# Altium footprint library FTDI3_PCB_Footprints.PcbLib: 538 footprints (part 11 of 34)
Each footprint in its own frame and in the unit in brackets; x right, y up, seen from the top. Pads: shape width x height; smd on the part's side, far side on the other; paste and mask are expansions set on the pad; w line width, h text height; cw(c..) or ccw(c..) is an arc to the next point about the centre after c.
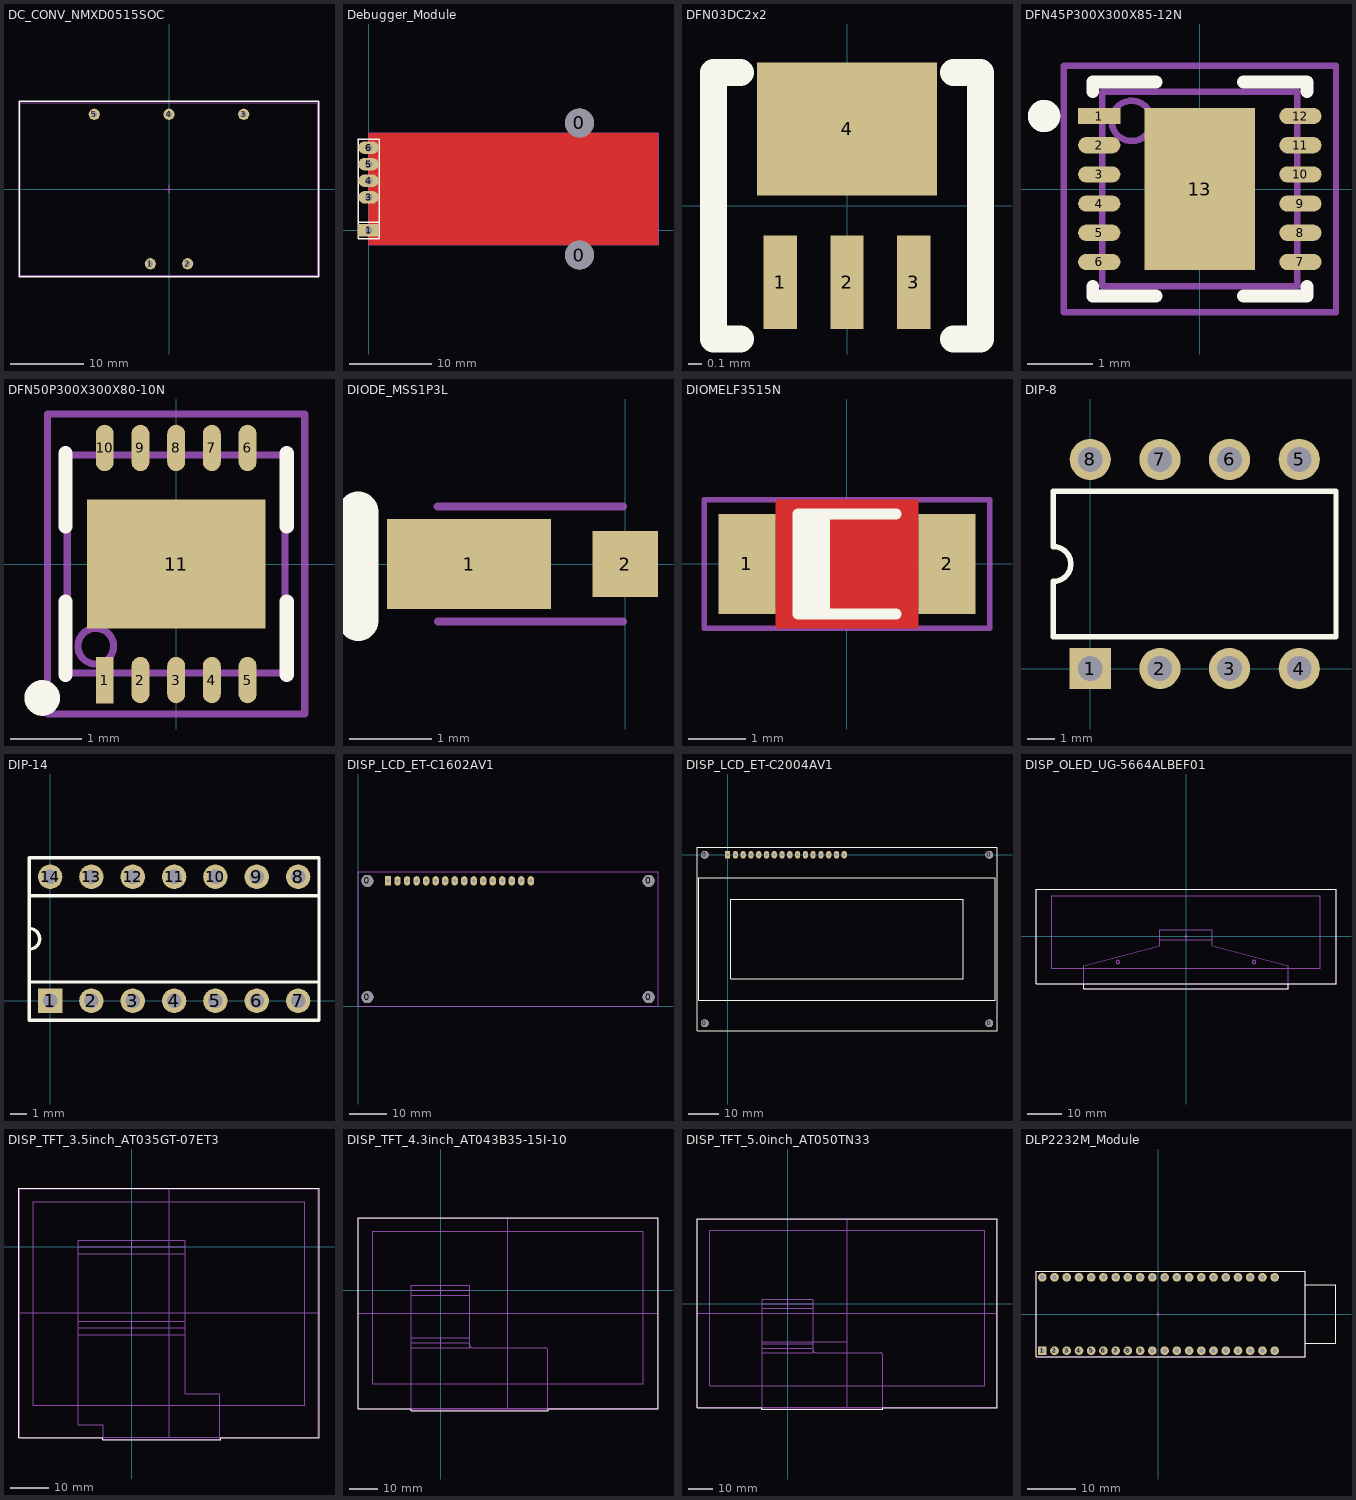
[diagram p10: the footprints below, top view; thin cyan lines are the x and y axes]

## DC_CONV_NMXD0515SOC [mil] "Isolated 5W Regulated Dual Output DC/DC Converter"
pads (5):
  round 60 hole 30: 1(-100,-400) 2(100,-400) 3(400,400) 4(0,400) 5(-400,400)
Top Overlay:
  lines w7.87: -802.76,-468.11 802.76,-468.11 802.76,468.5 -802.76,468.5 -802.76,-468.11
M13_Assembly_Info:
  lines w3.94: -797,-462.5 797,-462.5 797,462.5 -797,462.5 -797,-462.5
M15_Country_Yard:
  lines w3.94: -19.68,0 19.68,0 ; 0,-19.68 0,19.68

## Debugger_Module [mm] "VNC2 Debugger Module"
pads (7):
  round 3.5 hole 3.5 unplated: 0(25.5,-3) 0(25.5,13)
  rect 2.5x1.5 hole 0.9: 1(0,0)
  oval 2.5x1.5 hole 0.9: 3(0,4) 4(0,6) 5(0,8) 6(0,10)
Top Layer:
  pour cut-out: 0,-1.75 35,-1.75 35,11.75 0,11.75
Top Overlay:
  lines w0.2: -1.28,11 1.26,11 ; -1.27,11 -1.27,-1 1.27,-1 1.27,11 ; -1.26,0.98 1.28,0.98
M13_Assembly_Info:
  lines w0.2: 24,-1.75 24,11.75 ; 27,-1.75 27,11.75 ; 0,-1.75 35,-1.75 35,11.75 0,11.75 0,-1.75
3D body: height 1.88, standoff 0, extent 0,-1.75 35,11.75

## DFN03DC2x2 [mm]
pads (4):
  rect 0.25x0.7 smd: 1(-0.5,-0.575) 2(0,-0.575) 3(0.5,-0.575)
  rect 1.35x1 smd: 4(0,0.575)
Top Overlay:
  lines w0.203: -0.8,-1 -1,-1 -1,1 -0.8,1 ; 0.8,-1 1,-1 1,1 0.8,1

## DFN45P300X300X85-12N [mm] "DFN, 12-Leads, Body 3.0x3.0mm (max), Pitch 0.45mm, IPC Medium Density"
height 0.85
pads (13):
  rect 0.65x0.25 smd: 1(-1.55,1.125)
  oval 0.65x0.25 smd: 2(-1.55,0.675) 3(-1.55,0.225) 4(-1.55,-0.225) 5(-1.55,-0.675) 6(-1.55,-1.125) 7(1.55,-1.125) 8(1.55,-0.675) 9(1.55,-0.225) 10(1.55,0.225) 11(1.55,0.675) 12(1.55,1.125)
  rect 1.7x2.5 smd: 13(0,0)
Top Overlay:
  circle w0.25: c-2.4,1.125 r0.125
  lines w0.2: -1.65,-1.5 -1.65,-1.65 -0.675,-1.65 ; -1.65,1.5 -1.65,1.65 -0.675,1.65 ; 0.675,-1.65 1.65,-1.65 1.65,-1.5 ; 0.675,1.65 1.65,1.65 1.65,1.5
M13_Assembly_Info:
  circle w0.1: c-1.05,1.05 r0.31
  lines w0.1: -1.5,-1.5 1.5,-1.5 1.5,1.5 -1.5,1.5 -1.5,-1.5
M15_Country_Yard:
  lines w0.1: -0.5,0 0.5,0 ; 0,-0.5 0,0.5 ; -2.1,-1.9 2.1,-1.9 2.1,1.9 -2.1,1.9 -2.1,-1.9
3D body: height 0.85, standoff 0.02, extent -1.5,-1.5 1.5,1.5

## DFN50P300X300X80-10N [mm] "DFN, 10-Leads, Body 3.0x3.0mm (max), Pitch 0.50mm, IPC Medium Density"
height 0.8
pads (11):
  rect 0.25x0.65 smd: 1(-1,-1.625)
  oval 0.25x0.65 smd: 2(-0.5,-1.625) 3(0,-1.625) 4(0.5,-1.625) 5(1,-1.625) 6(1,1.625) 7(0.5,1.625) 8(0,1.625) 9(-0.5,1.625) 10(-1,1.625)
  rect 2.5x1.8 smd paste+0: 11(0,0)
Top Overlay:
  circle w0.25: c-1.875,-1.875 r0.125
  lines w0.2: -1.55,-1.55 -1.55,-0.525 ; -1.55,0.525 -1.55,1.55 ; 1.55,-1.55 1.55,-0.525 ; 1.55,0.525 1.55,1.55
M13_Assembly_Info:
  circle w0.1: c-1.125,-1.15 r0.25
  lines w0.1: -1.525,-1.525 1.525,-1.525 1.525,1.525 -1.525,1.525 -1.525,-1.525
M15_Country_Yard:
  lines w0.1: -0.5,0 0.5,0 ; 0,-0.5 0,0.5 ; -1.8,-2.1 1.8,-2.1 1.8,2.1 -1.8,2.1 -1.8,-2.1
3D body: height 0.8, standoff 0.05, extent -1.525,-1.525 1.525,1.525

## DIODE_MSS1P3L [mm] "DIODE_MSS1P3L MICRO_SMP"
height 0.65
pads (2):
  rect 2x1.1 smd: 1(-1.9,0)
  rect 0.8x0.8 smd: 2(0,0)
Top Overlay:
  lines w0.5: -3.251,-0.686 -3.251,0.635
M13_Assembly_Info:
  lines w0.1: -2.279,0.7 -0.025,0.7 ; -2.279,-0.7 -0.025,-0.7

## DIOMELF3515N [mm] "MELF Diode, 2-Leads, Body 3.5x1.5mm, IPC Medium Density"
height 1.6
pads (2):
  rect 1x1.75 smd: 1(-1.75,0) 2(1.75,0)
Top Layer:
  pour cut-out: -1.25,1.125 1.25,1.125 1.25,-1.125 -1.25,-1.125
Top Overlay:
  rectangle: -0.85,-0.875 -0.3,0.875
  lines w0.2: 0.85,-0.875 -0.85,-0.875 -0.85,0.875 0.85,0.875
M13_Assembly_Info:
  rectangle: -1.85,-0.8 -1.352,0.8
  lines w0.1: -1.85,-0.8 -1.85,0.8 1.85,0.8 1.85,-0.8 -1.85,-0.8
M15_Country_Yard:
  lines w0.1: -0.5,0 0.5,0 ; 0,-0.5 0,0.5 ; -2.5,-1.125 -2.5,1.125 2.5,1.125 2.5,-1.125 -2.5,-1.125
3D body: height 1.6, standoff 0, extent -1.85,-0.8 1.85,0.8

## DIP-8 [mm] "DIP; 8 Leads; Row Spacing 7.62 mm; Pitch 2.54 mm"
height 5.33
pads (8):
  rect 1.5x1.5 hole 0.9: 1(0,0)
  round 1.5 hole 0.9: 2(2.54,0) 3(5.08,0) 4(7.62,0) 5(7.62,7.62) 6(5.08,7.62) 7(2.54,7.62) 8(0,7.62)
Top Overlay:
  lines w0.2: -1.34,1.16 -1.34,3.175 ccw(c-1.34,3.81) -1.34,4.445 -1.34,6.46 8.96,6.46 8.96,1.16 -1.34,1.16

## DIP-14 [mm] "DIP; 14 Leads; Row Spacing 7.62 mm; Pitch 2.54 mm"
height 5.08
pads (14):
  rect 1.5x1.5 hole 0.9: 1(0,0)
  round 1.5 hole 0.9: 2(2.54,0) 3(5.08,0) 4(7.62,0) 5(10.16,0) 6(12.7,0) 7(15.24,0) 8(15.24,7.62) 9(12.7,7.62) 10(10.16,7.62) 11(7.62,7.62) 12(5.08,7.62) 13(2.54,7.62) 14(0,7.62)
Top Overlay:
  lines w0.2: -1.275,1.16 16.525,1.16 ; -1.275,3.175 ccw(c-1.275,3.81) -1.275,4.445 ; -1.275,6.46 16.525,6.46 ; -1.275,-1.2 16.525,-1.2 16.525,8.8 -1.275,8.8 -1.275,-1.2

## DISP_LCD_ET-C1602AV1 [mm] "LCD Module; 16x2"
height 14
pads (20):
  round 3.2 hole 3.2 unplated: 0(2.5,2.5) 0(2.5,33.5) 0(77.5,2.5) 0(77.5,33.5)
  rect 1.7x2.5 hole 0.9: 1(8,33.5)
  oval 1.7x2.5 hole 0.9: 2(10.54,33.5) 3(13.08,33.5) 4(15.62,33.5) 5(18.16,33.5) 6(20.7,33.5) 7(23.24,33.5) 8(25.78,33.5) 9(28.32,33.5) 10(30.86,33.5) 11(33.4,33.5) 12(35.94,33.5) 13(38.48,33.5) 14(41.02,33.5) 15(43.56,33.5) 16(46.1,33.5)
M13_Assembly_Info:
  lines w0.1: 0,0 80,0 80,36 0,36 0,0
3D body: height 12, standoff 10, extent 7.75,11.1 72.25,24.9
3D body: height 11.5, standoff 1.6, extent 4.35,4.55 75.65,31.45
3D body: height 4.14, standoff 2.54, extent 0,0 80,36

## DISP_LCD_ET-C2004AV1 [mm] "LCD Module; 20x4"
height 14
pads (20):
  round 2.54 hole 2.54: 0(-7.5,-55) 0(-7.5,0) 0(85.5,-55) 0(85.5,0)
  rect 1.7x2.5 hole 0.9: 1(0,0)
  oval 1.7x2.5 hole 0.9: 2(2.54,0) 3(5.08,0) 4(7.62,0) 5(10.16,0) 6(12.7,0) 7(15.24,0) 8(17.78,0) 9(20.32,0) 10(22.86,0) 11(25.4,0) 12(27.94,0) 13(30.48,0) 14(33.02,0) 15(35.56,0) 16(38.1,0)
Top Overlay:
  lines w0.2: -10,-57.5 88,-57.5 88,2.5 -10,2.5 -10,-57.5 ; -9.5,-47.5 87.5,-47.5 87.5,-7.5 -9.5,-7.5 -9.5,-47.5 ; 1,-40.5 1,-14.5 77,-14.5 77,-40.5 1,-40.5
3D body: height 12, standoff 10, extent 1,-40.5 77,-14.5
3D body: height 11.5, standoff 1.6, extent -9.5,-47.5 87.5,-7.5
3D body: height 1.6, standoff 0, extent -10,-57.5 88,2.5

## DISP_OLED_UG-5664ALBEF01 [mm] "UG-5664ALBEF01; Folding Type; OEL Display Module; 256x64 pixels; Monochrome; COF Package"
height 4
Top Overlay:
  lines w0.2: -30,-13.9 -30,-15.4 30,-15.4 30,-13.9 ; -44,-13.9 -44,13.9 44,13.9 44,-13.9 -44,-13.9
M15_Country_Yard:
  circle w0.2: c20,-7.5 r0.5
  circle w0.2: c-20,-7.5 r0.5
  lines w0.1: -30,-8.626 -30,-13.9 -30,-15.4 30,-15.4 30,-13.9 30,-8.625 7.752,-2.66 7.752,-1 ; -29.999,-8.626 -7.748,-2.66 -7.748,-1 ; -0.55,0 0.55,0 ; 0,-0.5 0,0.5 ; -7.748,-1 -7.748,2 7.752,2 7.752,-1 ; -7.748,-1 7.752,-1 ; -44,-13.9 44,-13.9 44,13.9 -44,13.9 -44,-13.9 ; -39.4,-9.275 39.375,-9.275 39.375,11.9 -39.4,11.9 -39.4,-9.275

## DISP_TFT_3.5inch_AT035GT-07ET3 [mm] "3.5\"; TFT Display; 320x240 pixels; with Touch-pad; A-TOPS ELECTRONICS COMPANY; Part No. AT035GT-07ET3"
height 4.05
Top Overlay:
  lines w0.2: -29.1,-49.25 -29.1,15.15 48.3,15.15 48.3,-49.25 22.9,-49.25 22.9,-49.81 -7.5,-49.81 -7.5,-49.25 -29.1,-49.25
M13_Assembly_Info:
  lines w0.1: -28.95,-49.1 -28.95,15 48.15,15 48.15,-49.1 -28.95,-49.1 ; -25.44,-40.88 -25.44,11.68 44.64,11.68 44.64,-40.88 -25.44,-40.88
M15_Country_Yard:
  lines w0.1: -28.95,-17.05 48.15,-17.05 ; -13.75,-20.9 13.75,-20.9 ; -13.75,-0.1 -13.75,-45.94 -7.35,-45.94 -7.35,-49.66 22.75,-49.66 22.75,-37.94 13.75,-37.94 13.75,-1.75 ; -13.75,0 13.75,0 ; 0,-22.65 0,-19.15 ; 0,-1.75 0,1.75 ; 9.6,-49.1 9.6,15 ; 13.75,-1.75 -13.75,-1.75 -13.75,1.75 13.75,1.75 13.75,-1.75 ; -13.75,-22.65 -13.75,-19.15 13.75,-19.15 13.75,-22.65 -13.75,-22.65
  text "For TFT cable on bottom of the PCB" at -9.63,-20.51 h0.8
  text "For TFT cable on top of the PCB" at -9.66,0.48 h0.8
  text "1" at 13.17,-2.79 h0.8
  text "54" at -13.43,-2.81 h0.8
  text "54" at -13.43,-23.71 h0.8
  text "1" at 13.17,-23.69 h0.8
3D body: height 8.1, standoff 3.6, extent -28.95,-49.1 48.15,15

## DISP_TFT_4.3inch_AT043B35-15I-10 [mm] "4.3\"; TFT Display; 480x272 pixels; with Touch-pad; A-TOPS ELECTRONICS COMPANY; Part No. AT043B35-15I-10"
height 4.2
Top Overlay:
  lines w0.2: -29.14,-41.9 -10.4,-41.9 -10.4,-42.46 37.95,-42.46 37.95,-41.9 76.65,-41.9 76.65,25.5 -29.14,25.5 -29.14,-41.9
M13_Assembly_Info:
  lines w0.1: 76.49,25.35 -29,25.35 -29,-41.75 76.5,-41.75 76.5,25.35 ; -23.984,-33.062 -23.984,20.798 71.416,20.798 71.416,-33.062 -23.984,-33.062
M15_Country_Yard:
  lines w0.1: -29,-8.2 76.5,-8.2 ; -10.31,-42.31 -10.31,1.75 10.19,1.75 10.19,-16.76 ; -10.31,-41.6 37.79,-41.6 76.5,-41.6 ; -10.31,-20.25 10.19,-20.25 10.19,-16.76 ; -10.31,-18.5 10.19,-18.5 ; -10.31,-16.75 10.18,-16.75 10.19,-16.76 ; -10.31,-1.75 10.19,-1.75 ; -10.31,0 10.19,0 ; -10.25,-42.31 37.79,-42.31 37.79,-21.25 ccw(c36.79,-21.25) 36.79,-20.25 ; 0,-20.25 0,-16.75 ; 0,-1.75 0,1.75 ; 10.19,-19.25 ccw(c11.19,-19.25) 11.19,-20.25 36.8,-20.25 ; 23.75,-41.75 23.75,25.65
  text "40" at 8.7,-20.05 h0.8
  text "1" at -10.1,-20.05 h0.8
  text "1" at -10,-1.5 h0.8
  text "40" at 8.7,-1.5 h0.8
  text "TFT cable - folded back" at -6.9,-18.05 h0.8
  text "TFT cable - straight" at -6.85,0.45 h0.8
3D body: height 4.5, standoff 0.5, extent -29,-41.75 76.5,25.35

## DISP_TFT_5.0inch_AT050TN33 [mm] "5\"; TFT Display; 480x272 pixels; with Touch-pad; A-TOPS ELECTRONICS COMPANY; Part No. AT050TN33"
height 4.25
Top Overlay:
  lines w0.2: -36.55,-41.9 -10.35,-41.9 -10.35,-42.46 38.45,-42.46 38.45,-41.9 84.45,-41.9 84.45,34.2 -36.55,34.2 -36.55,-41.9
M13_Assembly_Info:
  lines w0.1: -36.4,-41.75 -36.4,34.05 84.3,34.05 84.3,-41.75 -36.4,-41.75 ; -31.44,-33.086 -31.44,29.746 79.44,29.746 79.44,-33.086 -31.44,-33.086
M15_Country_Yard:
  lines w0.1: -36.4,-3.85 84.3,-3.85 ; -10.25,-42.16 -10.25,1.75 10.25,1.75 10.25,-19.7 -10.25,-19.7 ; -10.25,-17.95 10.25,-17.95 ; -10.25,-16.2 10.25,-16.2 ; -10.25,-15.3 23.95,-15.3 ; -10.25,-1.75 10.25,-1.75 ; -10.25,0 10.25,0 ; -10.2,-42.31 38.29,-42.31 38.29,-20.7 ccw(c37.29,-20.7) 37.29,-19.7 11.25,-19.7 cw(c11.25,-18.7) 10.25,-18.7 ; 0,-1.75 0,1.75 ; 0.05,-19.7 0.05,-16.2 ; 23.5,-3.81 24.5,-3.81 ; 23.95,-41.75 23.95,34.05 ; 24,-4.31 24,-3.31
  text "TFT cable - straight" at -6.85,0.5 h0.8
  text "TFT cable - folded back" at -6.9,-17.45 h0.8
  text "1" at -9.85,-1.5 h0.8
  text "40" at 8.64,-1.47 h0.8
  text "40" at 8.64,-19.47 h0.8
  text "1" at -9.85,-19.5 h0.8
3D body: height 4.5, standoff 0.5, extent -36.4,-41.75 84.3,34.05

## DLP2232M_Module [mm] "DIP; 40 Leads; Row Spacing 15.24 mm; Pitch 2.54 mm"
height 5.59
pads (40):
  rect 1.8x1.8 hole 0.9: 1(-24.13,-7.62)
  round 1.8 hole 0.9: 2(-21.59,-7.62) 3(-19.05,-7.62) 4(-16.51,-7.62) 5(-13.97,-7.62) 6(-11.43,-7.62) 7(-8.89,-7.62) 8(-6.35,-7.62) 9(-3.81,-7.62) 10(-1.27,-7.62) 11(1.27,-7.62) 12(3.81,-7.62) 13(6.35,-7.62) 14(8.89,-7.62) 15(11.43,-7.62) 16(13.97,-7.62) 17(16.51,-7.62) 18(19.05,-7.62) 19(21.59,-7.62) 20(24.13,-7.62) 21(24.13,7.62) 22(21.59,7.62) 23(19.05,7.62) 24(16.51,7.62) 25(13.97,7.62) 26(11.43,7.62) 27(8.89,7.62) 28(6.35,7.62) 29(3.81,7.62) 30(1.27,7.62) 31(-1.27,7.62) 32(-3.81,7.62) 33(-6.35,7.62) 34(-8.89,7.62) 35(-11.43,7.62) 36(-13.97,7.62) 37(-16.51,7.62) 38(-19.05,7.62) 39(-21.59,7.62) 40(-24.13,7.62)
Top Overlay:
  lines w0.2: 30.47,-6.1 36.86,-6.1 36.86,6.1 30.47,6.1 ; -25.43,-8.9 -25.43,8.9 30.47,8.9 30.47,-8.9 -25.43,-8.9
M13_Assembly_Info:
  lines w0.1: -25.43,-8.9 30.47,-8.9 30.47,8.9 -25.43,8.9 -25.43,-8.9
M15_Country_Yard:
  lines w0.1: -0.5,0 0.5,0 ; 0,-0.5 0,0.5
3D body: height 0, standoff 0, extent -25.43,-8.9 30.47,8.9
